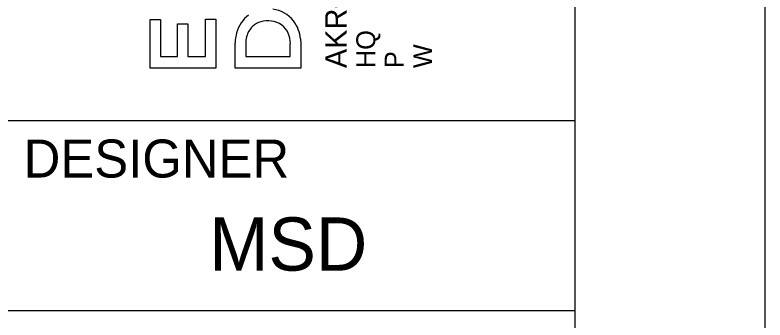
# Model space of a CAD drawing. Extents: x 0 to 34, y 0 to 22.
# Drawn here: x 32.027 to 34, y 2.475 to 3.278 of the extents above; entities that cross this region are included whole.
import ezdxf

# ---------------------------------------------------------------- set-up
doc = ezdxf.new("R2010")
doc.units = 0
for name, color, linetype in [('SH_Border', 7, 'Continuous'), ('SH_Cut_Line', 7, 'Continuous'), ('SH_Data', 7, 'Continuous')]:
    doc.layers.add(name, color=color, linetype=linetype)

msp = doc.modelspace()

# ---------------------------------------------------------------- linework, layer by layer
at = {"layer": 'SH_Border'}
for p, q in [((32, 3), (33.5, 3)), ((32, 2.5), (33.5, 2.5))]:
    msp.add_line(p, q, dxfattribs=at)
msp.add_lwpolyline([(1.5, 21.5), (33.5, 21.5), (33.5, 0.5), (1.5, 0.5)], close=True, dxfattribs=at)
at = {"layer": 'SH_Cut_Line'}
msp.add_lwpolyline([(0, 0), (34, 0), (34, 22), (0, 22)], close=True, dxfattribs=at)
at = {"layer": 'SH_Data'}
for p, q in [((32.383, 3.1379), (32.383, 3.266)), ((32.383, 3.266), (32.4101, 3.266)), ((32.4101, 3.266), (32.4101, 3.1683)), ((32.5286, 3.1683), (32.5286, 3.2672)), ((32.5286, 3.2672), (32.5557, 3.2672)), ((32.5557, 3.2672), (32.5557, 3.1379)), ((32.455, 3.1683), (32.455, 3.2549)), ((32.455, 3.2549), (32.4822, 3.2549)), ((32.4822, 3.2549), (32.4822, 3.1683)), ((32.6064, 3.138), (32.6064, 3.204)), ((32.6347, 3.2118), (32.6341, 3.2023)), ((32.6341, 3.2023), (32.6341, 3.1684)), ((32.7515, 3.1683), (32.7515, 3.2024)), ((32.7785, 3.215), (32.7792, 3.2021)), ((32.7792, 3.2021), (32.7792, 3.138)), ((32.4101, 3.1683), (32.455, 3.1683)), ((32.4822, 3.1683), (32.5286, 3.1683)), ((32.6341, 3.1684), (32.7515, 3.1683)), ((32.5557, 3.1379), (32.383, 3.1379)), ((32.7792, 3.138), (32.6064, 3.138))]:
    msp.add_line(p, q, dxfattribs=at)
msp.add_lwpolyline([(32.383, 3.1379), (32.383, 3.266), (32.4101, 3.266), (32.4101, 3.1683), (32.455, 3.1683), (32.455, 3.2549), (32.4822, 3.2549), (32.4822, 3.1683), (32.5286, 3.1683), (32.5286, 3.2672), (32.5557, 3.2672), (32.5557, 3.1379)], close=True, dxfattribs=at)
for points in [[(32.7785, 3.215), (32.7792, 3.2021), (32.7792, 3.138), (32.6064, 3.138)], [(32.6064, 3.138), (32.6064, 3.204)], [(32.6347, 3.2118), (32.6341, 3.2023), (32.6341, 3.1684), (32.7515, 3.1683), (32.7515, 3.2024)]]:
    msp.add_lwpolyline(points, dxfattribs=at)
for centre, radius, start, end in [((32.6939, 3.2089), 0.0865, 127.2362, 165.148), ((32.6939, 3.2089), 0.0865, 127.2362, 165.148), ((32.6946, 3.2113), 0.0827, 37.8521, 82.402), ((32.6946, 3.2113), 0.0827, 37.8521, 82.402), ((32.6889, 3.2078), 0.054, 106.1881, 157.3861), ((32.6889, 3.2078), 0.054, 106.1881, 157.3861), ((32.6928, 3.1986), 0.0639, 55.6727, 107.2093), ((32.6928, 3.1986), 0.0639, 55.6727, 107.2093), ((32.6859, 3.2057), 0.0931, 5.7333, 37.304), ((32.6859, 3.2057), 0.0931, 5.7333, 37.304), ((32.6929, 3.205), 0.0587, 357.4662, 52.2665), ((32.6929, 3.205), 0.0587, 357.4662, 52.2665), ((32.7143, 3.2028), 0.1078, 164.7861, 179.3704), ((32.7143, 3.2028), 0.1078, 164.7861, 179.3704), ((32.6983, 3.2039), 0.0641, 157.3571, 172.9275), ((32.6983, 3.2039), 0.0641, 157.3571, 172.9275)]:
    msp.add_arc(centre, radius, start, end, dxfattribs=at)

# ---------------------------------------------------------------- texts
for s, height, p in [('AKRON / CLEVELAND / COLUMBUS', 0.056969, (32.9001, 3.138)), ('HQ ', 0.04985, (32.9749, 3.138)), ('W', 0.0498, (33.1244, 3.138)), ('P', 0.0498, (33.0497, 3.138))]:
    msp.add_text(s, height=height, rotation=90, dxfattribs=at).set_placement(p)
for s, height, p in [('DESIGNER', 0.1, (32.05, 2.85)), ('MSD', 0.14, (32.5379, 2.605))]:
    msp.add_text(s, height=height, dxfattribs=at).set_placement(p)

doc.saveas('drawing.dxf')
